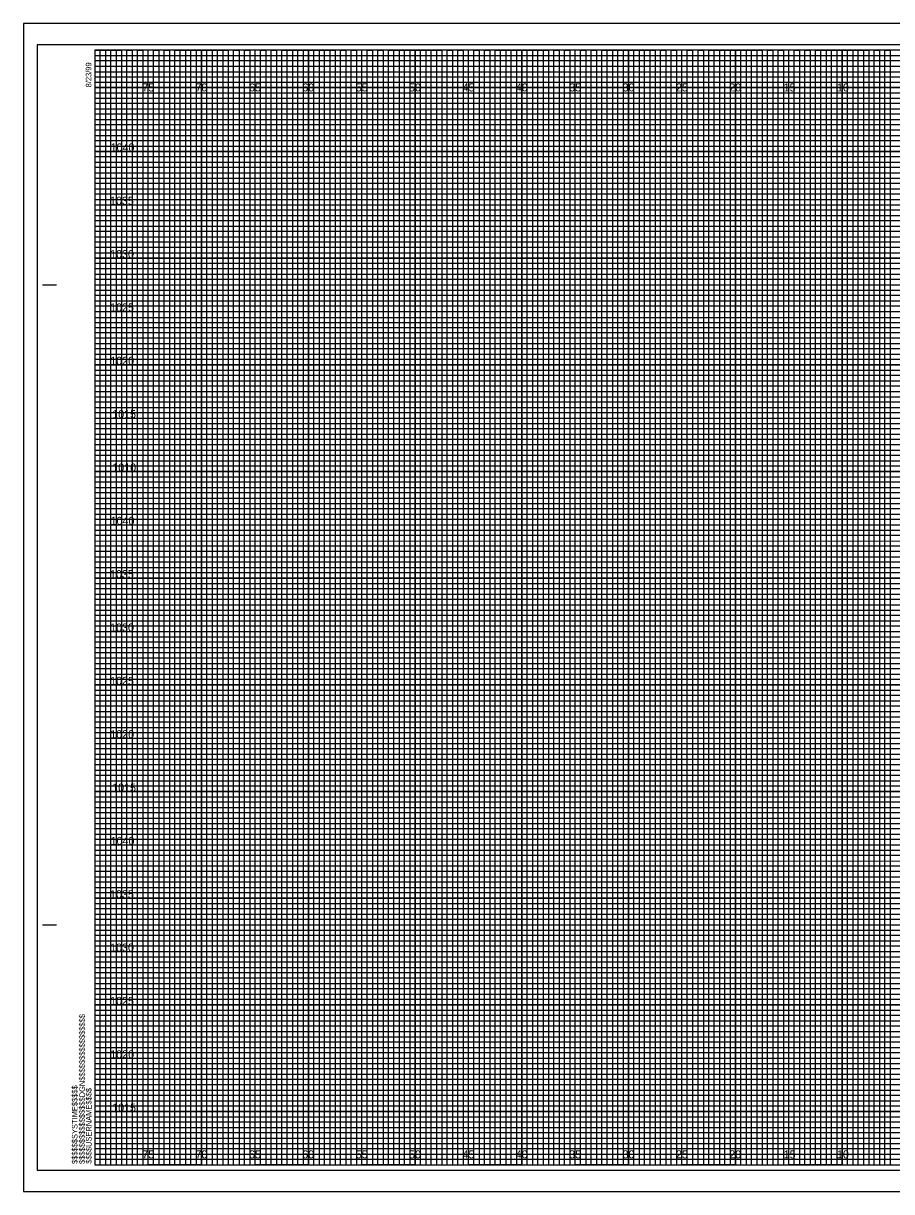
# Model space of a CAD drawing. Extents: x -7 to 162, y -2 to 987.
# Drawn here: x -6.7 to 74.6, y 107.5 to 217 of the extents above; entities that cross this region are included whole.
import ezdxf

# ---------------------------------------------------------------- set-up
doc = ezdxf.new("R2010")
doc.units = 0
for name, color, linetype in [('Exist Cross Section Cell', 7, 'Continuous'), ('Exist XS Center Line Elevation Label', 7, 'Continuous'), ('Exist XS Ground Line', 7, 'Continuous'), ('Prop CMT Concrete Structures', 7, 'Continuous'), ('Prop CMT Guardrail Widen Shoulder', 7, 'Continuous'), ('Prop CMT Pvmt Course 1', 7, 'Continuous'), ('Prop CMT Pvmt Surface', 7, 'Continuous'), ('Prop CMT Shld Paved Course 1', 7, 'Continuous'), ('Prop CMT Slope Grass', 7, 'Continuous'), ('Prop CMT Subgrade Earthwork', 7, 'Continuous'), ('Typical Text Label CELL', 7, 'Continuous')]:
    doc.layers.add(name, color=color, linetype=linetype)

msp = doc.modelspace()

# ---------------------------------------------------------------- linework, layer by layer
at = {"layer": 'Exist XS Center Line Elevation Label'}
for points in [[(0, 214.5), (2.5, 214.5), (2.5, 110), (7.5, 110), (7.5, 214.5), (12.5, 214.5), (12.5, 110), (17.5, 110), (17.5, 214.5), (22.5, 214.5), (22.5, 110), (27.5, 110), (27.5, 214.5), (32.5, 214.5), (32.5, 110), (37.5, 110), (37.5, 214.5), (42.5, 214.5), (42.5, 110), (47.5, 110), (47.5, 214.5), (52.5, 214.5), (52.5, 110), (57.5, 110), (57.5, 214.5), (62.5, 214.5), (62.5, 110), (67.5, 110), (67.5, 214.5), (72.5, 214.5), (72.5, 110), (77.5, 110)], [(0, 212), (137.5, 212)], [(0, 202.5), (160, 202.5), (160, 207.5), (0, 207.5)], [(0, 192.5), (160, 192.5), (160, 197.5), (0, 197.5)], [(0, 182.5), (160, 182.5), (160, 187.5), (0, 187.5)], [(0, 172.5), (160, 172.5), (160, 177.5), (0, 177.5)], [(0, 162.5), (160, 162.5), (160, 167.5), (0, 167.5)], [(0, 152.5), (160, 152.5), (160, 157.5), (0, 157.5)], [(0, 142.5), (160, 142.5), (160, 147.5), (0, 147.5)], [(0, 132.5), (160, 132.5), (160, 137.5), (0, 137.5)], [(0, 122.5), (160, 122.5), (160, 127.5), (0, 127.5)], [(0, 112.5), (160, 112.5), (160, 117.5), (0, 117.5)]]:
    msp.add_lwpolyline(points, dxfattribs=at)
at = {"layer": 'Exist XS Ground Line'}
for p, q in [((5, 214.5), (0, 214.5)), ((5, 110), (5, 214.5)), ((15, 214.5), (10, 214.5)), ((10, 214.5), (10, 110)), ((15, 110), (15, 214.5)), ((25, 214.5), (20, 214.5)), ((20, 214.5), (20, 110)), ((25, 110), (25, 214.5)), ((35, 214.5), (30, 214.5)), ((30, 214.5), (30, 110)), ((35, 110), (35, 214.5)), ((45, 214.5), (40, 214.5)), ((40, 214.5), (40, 110)), ((45, 110), (45, 214.5)), ((55, 214.5), (50, 214.5)), ((50, 214.5), (50, 110)), ((55, 110), (55, 214.5)), ((65, 214.5), (60, 214.5)), ((60, 214.5), (60, 110)), ((65, 110), (65, 214.5)), ((75, 214.5), (70, 214.5)), ((70, 214.5), (70, 110)), ((10, 110), (5, 110)), ((20, 110), (15, 110)), ((30, 110), (25, 110)), ((40, 110), (35, 110)), ((50, 110), (45, 110)), ((60, 110), (55, 110)), ((70, 110), (65, 110))]:
    msp.add_line(p, q, dxfattribs=at)
for points in [[(0, 210), (160, 210), (160, 205), (0, 205)], [(0, 200), (160, 200), (160, 195), (0, 195)], [(0, 190), (160, 190), (160, 185), (0, 185)], [(0, 180), (160, 180), (160, 175), (0, 175)], [(0, 170), (160, 170), (160, 165), (0, 165)], [(0, 160), (160, 160), (160, 155), (0, 155)], [(0, 150), (160, 150), (160, 145), (0, 145)], [(0, 140), (160, 140), (160, 135), (0, 135)], [(0, 130), (160, 130), (160, 125), (0, 125)], [(0, 120), (160, 120), (160, 115), (0, 115)]]:
    msp.add_lwpolyline(points, dxfattribs=at)
at = {"layer": 'Prop CMT Concrete Structures'}
for p, q in [((5, 110), (5, 214.5)), ((10, 110), (10, 214.5)), ((15, 110), (15, 214.5)), ((20, 110), (20, 214.5)), ((25, 110), (25, 214.5)), ((30, 110), (30, 214.5)), ((35, 110), (35, 214.5)), ((40, 110), (40, 214.5)), ((45, 110), (45, 214.5)), ((50, 110), (50, 214.5)), ((55, 110), (55, 214.5)), ((60, 110), (60, 214.5)), ((65, 110), (65, 214.5)), ((70, 110), (70, 214.5)), ((0, 210), (160, 210)), ((0, 205), (160, 205)), ((0, 200), (160, 200)), ((0, 195), (160, 195)), ((0, 190), (160, 190)), ((0, 185), (160, 185)), ((0, 180), (160, 180)), ((0, 175), (160, 175)), ((0, 170), (160, 170)), ((0, 165), (160, 165)), ((0, 160), (160, 160)), ((0, 155), (160, 155)), ((0, 150), (160, 150)), ((0, 145), (160, 145)), ((0, 140), (160, 140)), ((0, 135), (160, 135)), ((0, 130), (160, 130)), ((0, 125), (160, 125)), ((0, 120), (160, 120)), ((0, 115), (160, 115))]:
    msp.add_line(p, q, dxfattribs=at)
at = {"layer": 'Prop CMT Guardrail Widen Shoulder'}
for p, q in [((161.65, 217), (-6.7, 217)), ((-6.7, 217), (-6.7, 107.5)), ((-6.7, 107.5), (161.65, 107.5))]:
    msp.add_line(p, q, dxfattribs=at)
at = {"layer": 'Prop CMT Pvmt Course 1'}
msp.add_lwpolyline([(-6.7, 107.5), (161.65, 107.5), (161.65, 217), (-6.7, 217)], close=True, dxfattribs=at)
at = {"layer": 'Prop CMT Pvmt Surface'}
for points in [[(0, 110), (0.5, 110), (0.5, 214.5), (1, 214.5), (1, 110)], [(1, 110), (1.5, 110), (1.5, 214.5), (2, 214.5), (2, 110)], [(2.5, 110), (3, 110), (3, 214.5), (3.5, 214.5), (3.5, 110)], [(3.5, 110), (4, 110), (4, 214.5), (4.5, 214.5), (4.5, 110)], [(5, 110), (5.5, 110), (5.5, 214.5), (6, 214.5), (6, 110)], [(6, 110), (6.5, 110), (6.5, 214.5), (7, 214.5), (7, 110)], [(7.5, 110), (8, 110), (8, 214.5), (8.5, 214.5), (8.5, 110)], [(8.5, 110), (9, 110), (9, 214.5), (9.5, 214.5), (9.5, 110)], [(10, 110), (10.5, 110), (10.5, 214.5), (11, 214.5), (11, 110)], [(11, 110), (11.5, 110), (11.5, 214.5), (12, 214.5), (12, 110)], [(12.5, 110), (13, 110), (13, 214.5), (13.5, 214.5), (13.5, 110)], [(13.5, 110), (14, 110), (14, 214.5), (14.5, 214.5), (14.5, 110)], [(15, 110), (15.5, 110), (15.5, 214.5), (16, 214.5), (16, 110)], [(16, 110), (16.5, 110), (16.5, 214.5), (17, 214.5), (17, 110)], [(17.5, 110), (18, 110), (18, 214.5), (18.5, 214.5), (18.5, 110)], [(18.5, 110), (19, 110), (19, 214.5), (19.5, 214.5), (19.5, 110)], [(20, 110), (20.5, 110), (20.5, 214.5), (21, 214.5), (21, 110)], [(21, 110), (21.5, 110), (21.5, 214.5), (22, 214.5), (22, 110)], [(22.5, 110), (23, 110), (23, 214.5), (23.5, 214.5), (23.5, 110)], [(23.5, 110), (24, 110), (24, 214.5), (24.5, 214.5), (24.5, 110)], [(25, 110), (25.5, 110), (25.5, 214.5), (26, 214.5), (26, 110)], [(26, 110), (26.5, 110), (26.5, 214.5), (27, 214.5), (27, 110)], [(27.5, 110), (28, 110), (28, 214.5), (28.5, 214.5), (28.5, 110)], [(28.5, 110), (29, 110), (29, 214.5), (29.5, 214.5), (29.5, 110)], [(30, 110), (30.5, 110), (30.5, 214.5), (31, 214.5), (31, 110)], [(31, 110), (31.5, 110), (31.5, 214.5), (32, 214.5), (32, 110)], [(32.5, 110), (33, 110), (33, 214.5), (33.5, 214.5), (33.5, 110)], [(33.5, 110), (34, 110), (34, 214.5), (34.5, 214.5), (34.5, 110)], [(35, 110), (35.5, 110), (35.5, 214.5), (36, 214.5), (36, 110)], [(36, 110), (36.5, 110), (36.5, 214.5), (37, 214.5), (37, 110)], [(37.5, 110), (38, 110), (38, 214.5), (38.5, 214.5), (38.5, 110)], [(38.5, 110), (39, 110), (39, 214.5), (39.5, 214.5), (39.5, 110)], [(40, 110), (40.5, 110), (40.5, 214.5), (41, 214.5), (41, 110)], [(41, 110), (41.5, 110), (41.5, 214.5), (42, 214.5), (42, 110)], [(42.5, 110), (43, 110), (43, 214.5), (43.5, 214.5), (43.5, 110)], [(43.5, 110), (44, 110), (44, 214.5), (44.5, 214.5), (44.5, 110)], [(45, 110), (45.5, 110), (45.5, 214.5), (46, 214.5), (46, 110)], [(46, 110), (46.5, 110), (46.5, 214.5), (47, 214.5), (47, 110)], [(47.5, 110), (48, 110), (48, 214.5), (48.5, 214.5), (48.5, 110)], [(48.5, 110), (49, 110), (49, 214.5), (49.5, 214.5), (49.5, 110)], [(50, 110), (50.5, 110), (50.5, 214.5), (51, 214.5), (51, 110)], [(51, 110), (51.5, 110), (51.5, 214.5), (52, 214.5), (52, 110)], [(52.5, 110), (53, 110), (53, 214.5), (53.5, 214.5), (53.5, 110)], [(53.5, 110), (54, 110), (54, 214.5), (54.5, 214.5), (54.5, 110)], [(55, 110), (55.5, 110), (55.5, 214.5), (56, 214.5), (56, 110)], [(56, 110), (56.5, 110), (56.5, 214.5), (57, 214.5), (57, 110)], [(57.5, 110), (58, 110), (58, 214.5), (58.5, 214.5), (58.5, 110)], [(58.5, 110), (59, 110), (59, 214.5), (59.5, 214.5), (59.5, 110)], [(60, 110), (60.5, 110), (60.5, 214.5), (61, 214.5), (61, 110)], [(61, 110), (61.5, 110), (61.5, 214.5), (62, 214.5), (62, 110)], [(62.5, 110), (63, 110), (63, 214.5), (63.5, 214.5), (63.5, 110)], [(63.5, 110), (64, 110), (64, 214.5), (64.5, 214.5), (64.5, 110)], [(65, 110), (65.5, 110), (65.5, 214.5), (66, 214.5), (66, 110)], [(66, 110), (66.5, 110), (66.5, 214.5), (67, 214.5), (67, 110)], [(67.5, 110), (68, 110), (68, 214.5), (68.5, 214.5), (68.5, 110)], [(68.5, 110), (69, 110), (69, 214.5), (69.5, 214.5), (69.5, 110)], [(70, 110), (70.5, 110), (70.5, 214.5), (71, 214.5), (71, 110)], [(71, 110), (71.5, 110), (71.5, 214.5), (72, 214.5), (72, 110)], [(72.5, 110), (73, 110), (73, 214.5), (73.5, 214.5), (73.5, 110)], [(73.5, 110), (74, 110), (74, 214.5), (74.5, 214.5), (74.5, 110)]]:
    msp.add_lwpolyline(points, dxfattribs=at)
at = {"layer": 'Prop CMT Shld Paved Course 1'}
for p, q in [((0, 214), (130, 214)), ((130, 213.49), (0, 213.49)), ((0, 213.49), (0, 213)), ((0, 213), (130, 213)), ((130, 212.44), (0, 212.44)), ((0, 212.44), (0, 211.5)), ((0, 211.5), (160, 211.5))]:
    msp.add_line(p, q, dxfattribs=at)
for points in [[(0, 211), (135, 211), (160, 211), (160, 211), (0, 211)], [(0, 210.5), (160, 210.5), (160, 209.5), (0, 209.5)], [(0, 209), (160, 209), (160, 208.5), (0, 208.49)], [(0, 208), (160, 208), (160, 207), (0, 207)], [(0, 206.5), (160, 206.5), (160, 206), (0, 206)], [(0, 205.5), (160, 205.5), (160, 204.5), (0, 204.5)], [(0, 204), (160, 204), (160, 203.5), (0, 203.5)], [(0, 203), (160, 203), (160, 202), (0, 202)], [(0, 201.5), (160, 201.5), (160, 201), (0, 201)], [(0, 200.5), (160, 200.5), (160, 199.5), (0, 199.5)], [(0, 199), (160, 199), (160, 198.5), (0, 198.5)], [(0, 198), (160, 198), (160, 196.97), (160, 196.5), (160, 196), (0, 196)], [(0, 197), (160, 197), (160, 196.5), (0, 196.5)], [(0, 195.5), (160, 195.5), (160, 194.5), (0, 194.52)], [(0, 194.52), (160, 194.5), (160, 194), (0, 194)], [(0, 193.5), (160, 193.5), (160, 193), (0, 193)], [(0, 192), (160, 192), (160, 191.5), (0, 191.5)], [(0, 191), (160, 191), (160, 190.5), (0, 190.5)], [(-0.04, 189.44), (160, 189.44), (160, 188.94), (-0.04, 188.94)], [(0, 188.5), (160, 188.5), (160, 188), (0, 188)], [(0, 187), (160, 187), (160, 186.5), (0, 186.5)], [(0, 186), (160, 186), (160, 185.5), (0, 185.5)], [(0, 184.5), (160, 184.5), (160, 184), (0, 184)], [(0, 183.5), (160, 183.5), (160, 183), (0, 183)], [(0, 182), (160, 182), (160, 181.5), (0, 181.5)], [(0, 181), (160, 181), (160, 180.5), (0, 180.5)], [(0, 179.5), (160, 179.5), (160, 178.99), (0, 179)], [(0, 178.5), (160, 178.5), (160, 178), (0, 178)], [(0, 177), (160, 177), (160, 176.5), (0, 176.5)], [(0, 176), (160, 176), (160, 175.5), (0, 175.5)], [(0, 174.5), (160, 174.5), (160, 174), (0, 174)], [(0, 173.5), (160, 173.5), (160, 173), (0, 173)], [(0, 172), (160, 172), (160, 171.5), (0, 171.5)], [(0, 171), (160, 171), (160, 170.5), (0, 170.5)], [(0, 169.5), (160, 169.5), (160, 169), (0, 169)], [(0, 168.5), (160.03, 168.46), (160, 168), (0, 168)], [(0, 167), (160, 167), (160, 166.5), (0, 166.5)], [(0, 166), (160, 166), (160, 165.5), (0, 165.5)], [(0, 164.5), (160, 164.5), (160, 164), (0, 164)], [(0, 163.5), (160, 163.5), (160, 163), (0, 163)], [(0, 162), (160, 162), (160, 161.5), (0, 161.5)], [(0, 161), (160, 161), (160, 160.5), (0, 160.5)], [(0, 159.5), (160, 159.5), (160, 159), (0, 159)], [(0, 158.5), (160, 158.5), (160, 158), (0, 158)], [(0, 157), (160, 157), (160, 156.5), (0, 156.5)], [(0, 156), (160, 156), (160, 155.5), (0, 155.5)], [(0, 154.5), (160, 154.5), (160, 154), (0, 154)], [(0, 153.5), (160, 153.5), (160, 153), (0, 153)], [(0, 152), (160, 152), (160, 151.5), (0, 151.5)], [(0, 151), (160, 151), (160, 150.5), (0, 150.5)], [(0, 149.5), (160, 149.5), (160, 148.99), (0, 149)], [(0, 148.5), (160, 148.5), (160, 148), (0, 148)], [(0, 147), (160, 147), (160, 146.5), (0, 146.5)], [(0, 146), (160, 146), (160, 145.5), (0, 145.5)], [(0, 144.5), (160, 144.5), (160, 144), (0, 144)], [(0, 143.5), (160, 143.5), (160, 143), (0, 143)], [(0, 142), (160, 142), (160, 141.5), (0, 141.5)], [(0, 141), (160, 141), (160, 140.5), (0, 140.5)], [(0, 139.5), (160, 139.5), (160, 139), (0, 139)], [(0, 138.5), (160.03, 138.46), (160, 138), (0, 138)], [(0, 137), (160, 137), (160, 136.5), (0, 136.5)], [(0, 136), (160, 136), (160, 135.5), (0, 135.5)], [(0, 134.5), (160, 134.5), (160, 134), (0, 134)], [(0, 133.5), (160, 133.5), (160, 133), (0, 133)], [(0, 132), (160, 132), (160, 131.5), (0, 131.5)], [(0, 131), (160, 131), (160, 130.5), (0, 130.5)], [(0, 129.5), (160, 129.5), (160, 129), (0, 129)], [(0, 128.5), (160, 128.5), (160, 128), (0, 128)], [(0, 127), (160, 127), (160, 126.5), (0, 126.5)], [(0, 126), (160, 126), (160, 125.5), (0, 125.5)], [(0, 124.5), (160, 124.5), (160, 124), (0, 124)], [(0, 123.5), (160, 123.5), (160, 123), (0, 123)], [(0, 122), (160, 122), (160, 121.5), (0, 121.5)], [(0, 121), (160, 121), (160, 120.5), (0, 120.5)], [(0, 119.5), (160, 119.5), (160, 119), (0, 119)], [(0, 118.5), (160, 118.5), (160, 118), (0, 118)], [(0, 117), (160, 117), (160, 116.5), (0, 116.5)], [(0, 116), (160, 116), (160, 115.5), (0, 115.5)], [(0, 114.5), (160, 114.5), (160, 114), (0, 114)], [(0, 113.5), (160, 113.5), (160, 113), (0, 113)], [(0, 112), (160, 112), (160, 111.5), (0, 111.5)], [(0, 111), (160, 111), (160, 110.5), (0, 110.5)]]:
    msp.add_lwpolyline(points, dxfattribs=at)
at = {"layer": 'Prop CMT Slope Grass'}
msp.add_lwpolyline([(-5.4, 109.5), (161.2, 109.5), (161.2, 215), (-5.4, 215)], close=True, dxfattribs=at)
at = {"layer": 'Prop CMT Subgrade Earthwork'}
for p, q in [((-4.9, 192.5), (-3.65, 192.5)), ((-4.85, 192.5), (-3.6, 192.5)), ((-4.9, 132.5), (-3.65, 132.5)), ((-4.85, 132.5), (-3.6, 132.5)), ((0, 110), (0, 110)), ((0, 110), (0, 110)), ((0, 110), (0, 110)), ((0, 110), (0, 110)), ((0, 110), (0, 110)), ((0, 110), (0, 110)), ((0, 110), (0, 110))]:
    msp.add_line(p, q, dxfattribs=at)
msp.add_lwpolyline([(160, 214.5), (0, 214.5), (0, 110), (160, 110)], close=True, dxfattribs=at)

# ---------------------------------------------------------------- texts
at = {"layer": 'Exist Cross Section Cell'}
for s, p in [('75', (4.44, 210.62)), ('70', (9.43, 210.62)), ('65', (14.44, 210.62)), ('60', (19.43, 210.62)), ('55', (24.44, 210.62)), ('50', (29.43, 210.62)), ('45', (34.44, 210.62)), ('40', (39.43, 210.62)), ('35', (44.44, 210.62)), ('30', (49.43, 210.62)), ('25', (54.44, 210.62)), ('20', (59.43, 210.62)), ('15', (64.53, 210.62)), ('10', (69.52, 210.62)), ('75', (4.44, 110.62)), ('70', (9.43, 110.62)), ('65', (14.44, 110.62)), ('60', (19.43, 110.62)), ('55', (24.44, 110.62)), ('50', (29.43, 110.62)), ('45', (34.44, 110.62)), ('40', (39.43, 110.62)), ('35', (44.44, 110.62)), ('30', (49.43, 110.62)), ('25', (54.44, 110.62)), ('20', (59.43, 110.62)), ('15', (64.53, 110.62)), ('10', (69.52, 110.62))]:
    msp.add_text(s, height=0.75, dxfattribs=at).set_placement(p)
at = {"layer": 'Prop CMT Subgrade Earthwork'}
for s, p in [('8/23/99', (-0.33, 211)), ('$$$$$$$$$$$$$$$$DGN$$$$$$$$$$$$$$$$', (-0.94, 110.09)), ('$$$$$$SYSTIME$$$$$', (-1.63, 110.09)), ('$$$$USERNAME$$$$', (-0.31, 110.12))]:
    msp.add_text(s, height=0.525, rotation=90, dxfattribs=at).set_placement(p)
at = {"layer": 'Typical Text Label CELL'}
for s, p in [('1040', (1.47, 205)), ('1035', (1.42, 200)), ('1030', (1.43, 195)), ('1025', (1.43, 190)), ('1020', (1.44, 185)), ('1015', (1.62, 180)), ('1010', (1.63, 175)), ('1040', (1.47, 170)), ('1035', (1.42, 165)), ('1030', (1.43, 160)), ('1025', (1.43, 155)), ('1020', (1.44, 150)), ('1015', (1.62, 145)), ('1040', (1.47, 140)), ('1035', (1.42, 135)), ('1030', (1.43, 130)), ('1025', (1.43, 125)), ('1020', (1.44, 120)), ('1015', (1.62, 115))]:
    msp.add_text(s, height=0.75, dxfattribs=at).set_placement(p)

doc.saveas('drawing.dxf')
